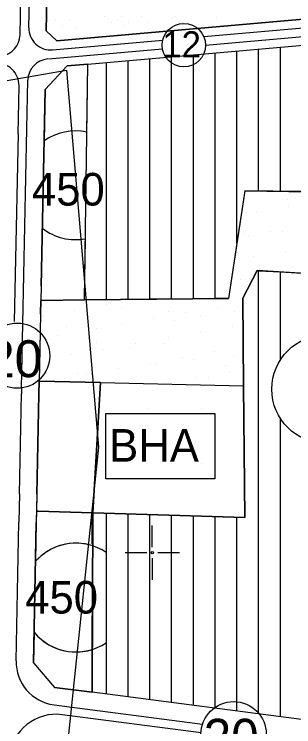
# Model space of a CAD drawing. Extents: x 419109 to 421295, y 4452223 to 4457798.
# Drawn here: x 420436.6 to 420565, y 4454419.9 to 4454747.5 of the extents above; entities that cross this region are included whole.
import ezdxf

# ---------------------------------------------------------------- set-up
doc = ezdxf.new("R2010")
doc.units = 0
for name, color, linetype in [('ADA', 7, 'Continuous'), ('ADAKENARI', 7, 'Continuous'), ('Default', 7, 'Continuous'), ('KALDIRIM', 7, 'Continuous'), ('KD_DAIRE', 7, 'Continuous'), ('KD_YGEN', 7, 'Continuous'), ('LJ_SEMBOL', 7, 'Continuous'), ('PAFTALAMA', 7, 'Continuous'), ('PL_AYA_PARK_DINLENME', 7, 'Continuous'), ('PL_K_BHA', 7, 'Continuous'), ('PL_K_TALI_IS_MRK', 7, 'Continuous'), ('PL_KON_MEV_350', 7, 'Continuous'), ('PL_KON_MEV_450', 7, 'Continuous'), ('SM_DAIRE', 7, 'Continuous'), ('SM_TAKS', 7, 'Continuous'), ('SN_KENTSEL_DONUSUM', 7, 'Continuous'), ('TR_ORTAYOGUNKONUT', 7, 'Continuous'), ('TR_PARKALANI', 7, 'Continuous'), ('TR_TALIISMERK', 7, 'Continuous'), ('TR_YONETIMMERK', 7, 'Continuous'), ('TR_YUKSEKYOGUNKONUT', 7, 'Continuous')]:
    doc.layers.add(name, color=color, linetype=linetype)

# ---------------------------------------------------------------- blocks, each defined once
blk = doc.blocks.new('POINT_DISPLAY')
at = {"layer": 'Default'}
blk.add_line((0, 0), (0, 0), dxfattribs=at)

msp = doc.modelspace()

# ---------------------------------------------------------------- linework, layer by layer
at = {"layer": 'ADA'}
for p, q in [((420468.88, 4454616.18), (420470.44, 4454724.58)), ((420542.58, 4454666.29), (420534.98, 4454616.87)), ((420542.58, 4454666.29), (420632.64, 4454665.27)), ((420548.18, 4454629.65), (420541.57, 4454616.93)), ((420627.04, 4454625.07), (420548.18, 4454629.65)), ((420448.76, 4454615.98), (420468.88, 4454616.18)), ((420468.88, 4454616.18), (420534.98, 4454616.87)), ((420541.57, 4454616.93), (420541.97, 4454576.68)), ((420448.01, 4454578.86), (420476.17, 4454578.21)), ((420476.17, 4454578.21), (420472.69, 4454518.32)), ((420476.17, 4454578.21), (420541.97, 4454576.68)), ((420541.97, 4454576.68), (420542.58, 4454516.19)), ((420472.69, 4454518.32), (420472.42, 4454435.77)), ((420542.58, 4454516.19), (420472.69, 4454518.32))]:
    msp.add_line(p, q, dxfattribs=at)
at = {"layer": 'ADAKENARI'}
for p, q in [((420451.27, 4454739.93), (420452.77, 4454810.89)), ((420593.63, 4454747.49), (420456.15, 4454735.37)), ((420451.27, 4454739.93), (420456.15, 4454735.37)), ((420470.44, 4454724.58), (420592.05, 4454735.3)), ((420450.72, 4454712.86), (420460.89, 4454723.74)), ((420460.89, 4454723.74), (420470.44, 4454724.58)), ((420448.9, 4454622.48), (420450.72, 4454712.86)), ((420448.9, 4454622.48), (420448.76, 4454615.98)), ((420448.64, 4454609.69), (420448.76, 4454615.98)), ((420448.64, 4454609.69), (420448.15, 4454585.82)), ((420448.15, 4454585.82), (420448.01, 4454578.86)), ((420447.89, 4454572.82), (420448.01, 4454578.86)), ((420446.96, 4454526.83), (420447.89, 4454572.82)), ((420446.96, 4454526.83), (420446.7, 4454513.83)), ((420445.39, 4454449.29), (420446.7, 4454513.83)), ((420445.39, 4454449.29), (420455.11, 4454438.01)), ((420472.42, 4454435.77), (420455.11, 4454438.01)), ((420568.64, 4454423.32), (420472.42, 4454435.77))]:
    msp.add_line(p, q, dxfattribs=at)
at = {"layer": 'KALDIRIM'}
for p, q in [((420443.3, 4454741.35), (420444.96, 4454820.07)), ((420439.23, 4454738), (420440.79, 4454815.38)), ((420523.69, 4454737.3), (420593.1, 4454743.42)), ((420524.52, 4454733.36), (420592.58, 4454739.36)), ((420454.18, 4454731.18), (420504.79, 4454735.64)), ((420452.36, 4454727), (420504.66, 4454731.61)), ((420440.55, 4454605.29), (420442.81, 4454717.2)), ((420438.31, 4454692.56), (420438.76, 4454714.68)), ((420438.31, 4454692.56), (420436.57, 4454606.29)), ((420439.95, 4454575.67), (420440.55, 4454605.29)), ((420439.95, 4454575.67), (420439.89, 4454572.98)), ((420438.96, 4454526.99), (420439.89, 4454572.98)), ((420438.96, 4454526.99), (420438.7, 4454514)), ((420437.41, 4454450.21), (420438.7, 4454514)), ((420454.84, 4454429.98), (420523.13, 4454421.14)), ((420458.52, 4454425.47), (420522.39, 4454417.2))]:
    msp.add_line(p, q, dxfattribs=at)
for centre, radius, start, end in [((420453.3, 4454741.14), 10, 178.7929, 275.0382), ((420429.23, 4454738.2), 10, 278.0547, 358.8413), ((420452.81, 4454717), 10, 95.0382, 178.8413), ((420428.76, 4454714.89), 10, 358.8413, 95.0366), ((420457.41, 4454449.81), 20, 178.8413, 262.6284), ((420455.77, 4454404.17), 21.47, 82.6284, 174.8004)]:
    msp.add_arc(centre, radius, start, end, dxfattribs=at)
at = {"layer": 'KD_DAIRE'}
for centre, radius in [((420514.52, 4454733.31), 10), ((420437.88, 4454590.53), 15), ((420537.38, 4454416.46), 15)]:
    msp.add_circle(centre, radius, dxfattribs=at)
at = {"layer": 'LJ_SEMBOL'}
msp.add_line((420478.7, 4454533.94), (420478.7, 4454533.94), dxfattribs=at)
msp.add_lwpolyline([(420478.7, 4454563.94), (420528.7, 4454563.94), (420528.7, 4454533.94), (420478.7, 4454533.94), (420478.7, 4454563.94), (420528.7, 4454563.94)], dxfattribs=at)
at = {"layer": 'PAFTALAMA'}
for p, q in [((420500, 4454502.5), (420500, 4454512.5)), ((420487.5, 4454500), (420497.5, 4454500)), ((420500, 4454497.5), (420500, 4454487.5)), ((420502.5, 4454500), (420512.5, 4454500))]:
    msp.add_line(p, q, dxfattribs=at)
msp.add_circle((420500, 4454500), 0.5, dxfattribs=at)
at = {"layer": 'PL_AYA_PARK_DINLENME'}
for p, q in [((420452.77, 4454810.89), (420451.27, 4454739.93)), ((420456.15, 4454735.37), (420593.63, 4454747.49)), ((420451.27, 4454739.93), (420456.15, 4454735.37))]:
    msp.add_line(p, q, dxfattribs=at)
for points in [[(420568.88, 4454665.99), (420558.88, 4454666.1), (420548.88, 4454666.21), (420542.58, 4454666.29), (420538.88, 4454642.2), (420534.98, 4454616.87), (420528.88, 4454616.8), (420518.88, 4454616.7), (420508.88, 4454616.6), (420498.88, 4454616.49), (420488.88, 4454616.39), (420478.88, 4454616.29), (420468.88, 4454616.18), (420448.76, 4454615.98), (420448.64, 4454609.69), (420448.15, 4454585.82), (420448.01, 4454578.86), (420476.17, 4454578.21), (420541.97, 4454576.68), (420541.57, 4454616.93), (420548.18, 4454629.65), (420548.88, 4454629.61)], [(420548.88, 4454629.61), (420558.88, 4454629.03), (420568.88, 4454628.45)]]:
    msp.add_lwpolyline(points, dxfattribs=at)
at = {"layer": 'PL_K_BHA'}
msp.add_lwpolyline([(420476.17, 4454578.21), (420541.97, 4454576.68), (420542.58, 4454516.19), (420472.69, 4454518.32)], close=True, dxfattribs=at)
at = {"layer": 'PL_K_TALI_IS_MRK'}
msp.add_lwpolyline([(420446.8, 4454519.11), (420447.41, 4454519.09), (420452.41, 4454518.94), (420457.41, 4454518.79), (420462.41, 4454518.63), (420467.41, 4454518.48), (420472.41, 4454518.33), (420472.69, 4454518.32), (420476.17, 4454578.21), (420448.01, 4454578.86), (420447.89, 4454572.82), (420446.96, 4454526.83), (420446.8, 4454519.11)], dxfattribs=at)
at = {"layer": 'PL_KON_MEV_350'}
msp.add_lwpolyline([(420592.05, 4454735.3), (420661.73, 4454710.22), (420669.68, 4454696.94), (420640.51, 4454499.42), (420580.23, 4454505), (420568.64, 4454423.32), (420472.42, 4454435.77), (420472.69, 4454518.32), (420542.58, 4454516.19), (420541.97, 4454576.68), (420541.57, 4454616.93), (420548.18, 4454629.65), (420627.04, 4454625.07), (420632.64, 4454665.27), (420542.58, 4454666.29), (420534.98, 4454616.87), (420468.88, 4454616.18), (420470.44, 4454724.58)], close=True, dxfattribs=at)
at = {"layer": 'PL_KON_MEV_450'}
for points in [[(420448.76, 4454615.98), (420468.88, 4454616.18), (420470.44, 4454724.58), (420460.89, 4454723.74), (420450.72, 4454712.86), (420448.9, 4454622.48), (420448.76, 4454615.98)], [(420446.8, 4454519.11), (420446.7, 4454513.83), (420445.39, 4454449.29), (420455.11, 4454438.01), (420472.42, 4454435.77), (420472.69, 4454518.32), (420472.41, 4454518.33), (420467.41, 4454518.48), (420462.41, 4454518.63), (420457.41, 4454518.79), (420452.41, 4454518.94), (420447.41, 4454519.09), (420446.8, 4454519.11)]]:
    msp.add_lwpolyline(points, dxfattribs=at)
at = {"layer": 'SM_DAIRE'}
msp.add_circle((420579.93, 4454575.13), 25, dxfattribs=at)
for centre, start, end in [((420464.72, 4454668.9), 77.8183, 125.3651), ((420464.72, 4454668.9), 232.3174, 280.525), ((420464.93, 4454479.3), 56.1032, 138.0633), ((420464.93, 4454479.3), 219.6193, 303.8968)]:
    msp.add_arc(centre, 25, start, end, dxfattribs=at)
at = {"layer": 'SN_KENTSEL_DONUSUM'}
for p, q in [((420334.54, 4454700.27), (420460.6, 4454721.81)), ((420460.6, 4454721.81), (420475.35, 4454548.5)), ((420475.35, 4454548.5), (420429.24, 4454109.6))]:
    msp.add_line(p, q, dxfattribs=at)
at = {"layer": 'TR_ORTAYOGUNKONUT'}
for p, q in [((420528.88, 4454616.8), (420528.88, 4454729.73)), ((420538.88, 4454642.2), (420538.88, 4454730.61)), ((420548.88, 4454666.21), (420548.88, 4454731.49)), ((420558.88, 4454666.1), (420558.88, 4454732.38)), ((420488.88, 4454616.39), (420488.88, 4454726.2)), ((420498.88, 4454616.49), (420498.88, 4454727.09)), ((420508.88, 4454616.6), (420508.88, 4454727.97)), ((420518.88, 4454616.7), (420518.88, 4454728.85)), ((420478.88, 4454685.43), (420478.88, 4454725.32)), ((420478.88, 4454616.29), (420478.88, 4454685.43)), ((420548.88, 4454425.88), (420548.88, 4454629.61)), ((420558.88, 4454588.61), (420558.88, 4454629.03)), ((420558.88, 4454424.58), (420558.88, 4454561.64)), ((420478.88, 4454434.93), (420478.88, 4454518.13)), ((420488.88, 4454433.64), (420488.88, 4454517.83)), ((420498.88, 4454432.34), (420498.88, 4454517.52)), ((420508.88, 4454431.05), (420508.88, 4454517.22)), ((420518.88, 4454429.76), (420518.88, 4454516.91)), ((420528.88, 4454428.46), (420528.88, 4454516.61)), ((420538.88, 4454427.17), (420538.88, 4454516.31))]:
    msp.add_line(p, q, dxfattribs=at)
at = {"layer": 'TR_TALIISMERK'}
msp.add_lwpolyline([(420446.8, 4454519.11), (420447.41, 4454519.09), (420452.41, 4454518.94), (420457.41, 4454518.79), (420462.41, 4454518.63), (420467.41, 4454518.48), (420472.41, 4454518.33), (420472.69, 4454518.32), (420476.17, 4454578.21), (420448.01, 4454578.86), (420447.89, 4454572.82), (420446.96, 4454526.83), (420446.8, 4454519.11)], dxfattribs=at)
at = {"layer": 'TR_YUKSEKYOGUNKONUT'}
for p, q in [((420472.41, 4454504.05), (420472.41, 4454518.33)), ((420472.41, 4454435.77), (420472.41, 4454470.93))]:
    msp.add_line(p, q, dxfattribs=at)
for points in [[(420469.99, 4454693.34), (420470.44, 4454724.58), (420460.89, 4454723.74), (420450.72, 4454712.86), (420450.25, 4454689.29)], [(420449.44, 4454649.12), (420448.9, 4454622.48), (420448.76, 4454615.98), (420468.88, 4454616.18), (420469.28, 4454644.32)], [(420472.64, 4454503.08), (420472.69, 4454518.32), (420472.41, 4454518.33), (420467.41, 4454518.48), (420462.41, 4454518.63), (420457.41, 4454518.79), (420452.41, 4454518.94), (420447.41, 4454519.09), (420446.8, 4454519.11), (420446.7, 4454513.83), (420446.34, 4454496)], [(420445.68, 4454463.35), (420445.39, 4454449.29), (420455.11, 4454438.01), (420472.42, 4454435.77), (420472.41, 4454455.44)]]:
    msp.add_lwpolyline(points, dxfattribs=at)
for centre, start, end in [((420464.72, 4454668.9), 77.8183, 125.3651), ((420464.72, 4454668.9), 232.3174, 280.525), ((420464.93, 4454479.3), 72.0461, 138.0633), ((420464.93, 4454479.3), 219.6193, 287.4056)]:
    msp.add_arc(centre, 25, start, end, dxfattribs=at)

# ---------------------------------------------------------------- block references
at = {"layer": 'TR_PARKALANI', "xscale": 0.1, "yscale": 0.10000000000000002}
for p in [(420477.94, 4454746.64), (420485.83, 4454746.64), (420495.03, 4454746.64), (420509.49, 4454745.98), (420510.81, 4454746.64), (420515.89, 4454746.27), (420529.7, 4454746.27), (420455.58, 4454745.32), (420462.16, 4454744.66), (420481.05, 4454743.64), (420483.85, 4454745.32), (420488.94, 4454743.64), (420498.14, 4454743.64), (420512.61, 4454742.98), (420513.92, 4454743.64), (420458.69, 4454742.33), (420465.27, 4454741.67), (420486.96, 4454742.33), (420562.31, 4454662.23), (420562.55, 4454659.21), (420547.77, 4454656.61), (420554.43, 4454647.63), (420539.66, 4454645.02), (420542.27, 4454646.64), (420544.07, 4454645.14), (420559.71, 4454647.46), (420561.09, 4454638.65), (420546.32, 4454636.04), (420540.59, 4454625.45), (420478.03, 4454616.17), (420521.89, 4454616.48), (420479.12, 4454614.04), (420486.05, 4454612.52), (420530.1, 4454612.87), (420449.58, 4454608.83), (420450.22, 4454608.56), (420464.35, 4454611.43), (420507.58, 4454610.96), (420515.33, 4454610.27), (420522.35, 4454608.35), (420537.99, 4454610.67), (420485.78, 4454605.06), (420500.55, 4454607.66), (420510.4, 4454606.84), (420460.66, 4454604), (420471.01, 4454602.46), (420474.56, 4454602.88), (420536.76, 4454603.89), (420456.24, 4454599.85), (420507.22, 4454598.68), (420521.99, 4454601.29), (420474.56, 4454596.47), (420492.44, 4454596.08), (420504.97, 4454596.19), (420477.67, 4454593.48), (420489.33, 4454593.87), (420528.65, 4454592.31), (420462.9, 4454590.87), (420513.88, 4454589.7), (420518.88, 4454588.66), (420537.34, 4454590.29), (420448.13, 4454588.27), (420499.1, 4454587.1), (420501.51, 4454586.32), (420533.65, 4454586.05), (420465.67, 4454582.36), (420484.33, 4454584.5), (420535.31, 4454583.33), (420454.79, 4454579.29), (420456.31, 4454579.38), (420469.56, 4454581.89), (420471.95, 4454581.7), (420520.54, 4454580.73), (420525.85, 4454580.64), (420505.76, 4454578.12)]:
    msp.add_blockref('POINT_DISPLAY', p, dxfattribs=at)
at = {"layer": 'TR_YONETIMMERK', "xscale": 0.1, "yscale": 0.10000000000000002}
for p in [(420497.69, 4454566.19), (420522.69, 4454566.19), (420497.69, 4454541.19), (420522.69, 4454541.19)]:
    msp.add_blockref('POINT_DISPLAY', p, dxfattribs=at)

# ---------------------------------------------------------------- texts
at = {"layer": 'KD_YGEN'}
for s, height, p in [('12', 12, (420504.54, 4454727.7)), ('20', 17, (420424.11, 4454580.64)), ('20', 17, (420523.61, 4454406.56))]:
    msp.add_text(s, height=height, dxfattribs=at).set_placement(p)
at = {"layer": 'LJ_SEMBOL'}
msp.add_text('BHA', height=15, dxfattribs=at).set_placement((420480.18, 4454541.79))
at = {"layer": 'SM_TAKS'}
for p in [(420444.68, 4454659.57), (420441.59, 4454471.95)]:
    msp.add_text('450', height=15, dxfattribs=at).set_placement(p)

doc.saveas('drawing.dxf')
